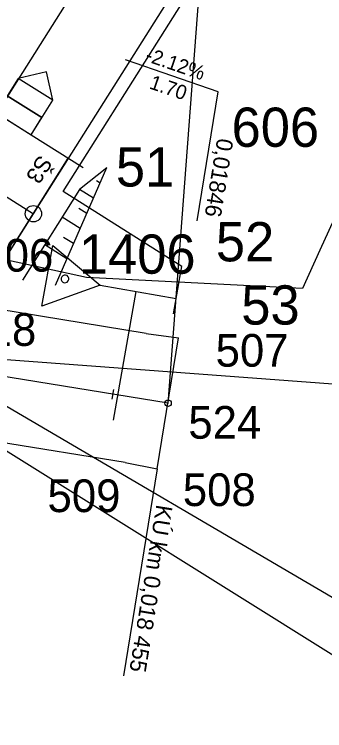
# Model space of a CAD drawing. Extents: x -743546 to -74, y -1128126 to -103.
# Drawn here: x -743168.98 to -743159.49, y -1127109.43 to -1127087.52 of the extents above; entities that cross this region are included whole.
import ezdxf

# ---------------------------------------------------------------- set-up
doc = ezdxf.new("R2010")
doc.units = 0
for name, color, linetype in [('_SVAH - Přesunutá', 7, 'Continuous'), ('_Zabezpečovací zařízení', 7, 'Continuous'), ('_Zabezpečovací zařízení_trasa', 7, 'Continuous'), ('bublina_fialová_čára_tenká', 7, 'Continuous'), ('KOMUNIKACE_KRAJNICE', 7, 'Continuous'), ('křížek', 7, 'Continuous'), ('křížky', 7, 'Continuous'), ('OSA_KOMUNIKACE', 7, 'Continuous'), ('OSA_POP', 7, 'Continuous'), ('SKLONOVNIKY', 7, 'Continuous'), ('SMER_VYS_VYROVNANI', 7, 'Continuous'), ('TRATIVOD', 7, 'Continuous'), ('Vrstva 53', 7, 'Continuous'), ('Vrstva 60', 7, 'Continuous')]:
    doc.layers.add(name, color=color, linetype=linetype)

# ---------------------------------------------------------------- blocks, each defined once
blk = doc.blocks.new('POINT_DISPLAY')
blk.add_line((0, 0), (0, 0))
blk = doc.blocks.new('AeccTickCircle')
blk.add_circle((0, 0), 0.5)

msp = doc.modelspace()

# ---------------------------------------------------------------- linework, layer by layer
at = {"layer": '_SVAH - Přesunutá'}
for p, q in [((-743166.364, -1127092.684), (-743166.469, -1127092.618)), ((-743166.567, -1127093.147), (-743166.987, -1127092.882)), ((-743166.77, -1127093.61), (-743167.012, -1127093.458)), ((-743166.973, -1127094.073), (-743167.521, -1127093.728)), ((-743167.176, -1127094.536), (-743167.482, -1127094.344)), ((-743167.379, -1127095), (-743168.055, -1127094.573))]:
    msp.add_line(p, q, dxfattribs=at)
for points in [[(-743167.343, -1127091.922), (-743169.607, -1127095.509)], [(-743166.158, -1127092.217), (-743166.987, -1127092.882), (-743168.735, -1127095.651)], [(-743166.161, -1127092.221), (-743167.737, -1127095.814)]]:
    msp.add_lwpolyline(points, dxfattribs=at)
at = {"layer": '_Zabezpečovací zařízení'}
for p, q in [((-743168.004, -1127089.286), (-743168.865, -1127089.483)), ((-743167.807, -1127090.147), (-743168.004, -1127089.286)), ((-743168.865, -1127089.483), (-743169.53, -1127090.542)), ((-743167.807, -1127090.147), (-743168.865, -1127089.483)), ((-743169.198, -1127090.012), (-743168.139, -1127090.677)), ((-743168.471, -1127091.206), (-743167.807, -1127090.147)), ((-743169.53, -1127090.542), (-743168.471, -1127091.206)), ((-743168.139, -1127096.449), (-743167.81, -1127094.588)), ((-743167.81, -1127094.588), (-743166.363, -1127095.804)), ((-743164.119, -1127096.681), (-743163.954, -1127095.75)), ((-743166.363, -1127095.804), (-743168.139, -1127096.449)), ((-743166.363, -1127095.804), (-743164.036, -1127096.216)), ((-743165.267, -1127095.997), (-743165.964, -1127099.936))]:
    msp.add_line(p, q, dxfattribs=at)
msp.add_lwpolyline([(-743168.471, -1127091.206), (-743168.139, -1127090.677), (-743169.198, -1127090.012), (-743169.53, -1127090.542), (-743168.471, -1127091.206)], dxfattribs=at)
for start, end in [(79.9608, 259.9608), (259.9608, 79.9608)]:
    msp.add_arc((-743167.437, -1127095.614), 0.118, start, end, dxfattribs=at)
at = {"layer": '_Zabezpečovací zařízení_trasa'}
for points in [[(-743164.036, -1127096.193), (-743163.862, -1127095.231), (-743167.492, -1127092.937), (-743158.53, -1127078.745)], [(-743168.471, -1127091.206), (-743166.88, -1127092.211)]]:
    msp.add_lwpolyline(points, dxfattribs=at)
at = {"layer": 'bublina_fialová_čára_tenká'}
for p, q in [((-743158.823, -1127027.044), (-743164.286, -1127099.423)), ((-743129.509, -1127122.8), (-743175.485, -1127095.847)), ((-743148.502, -1127099.644), (-743174.29, -1127097.707)), ((-743109.419, -1127138.306), (-743174.121, -1127097.814))]:
    msp.add_line(p, q, dxfattribs=at)
at = {"layer": 'KOMUNIKACE_KRAJNICE'}
for p, q in [((-743164.95, -1127097.281), (-743171.211, -1127096.261)), ((-743164.95, -1127097.281), (-743163.96, -1127097.421)), ((-743164.612, -1127101.425), (-743163.96, -1127097.421)), ((-743165.593, -1127101.229), (-743173.53, -1127099.936)), ((-743165.593, -1127101.229), (-743164.612, -1127101.425))]:
    msp.add_line(p, q, dxfattribs=at)
at = {"layer": 'OSA_KOMUNIKACE'}
msp.add_line((-743164.284, -1127099.415), (-743182.5, -1127096.45), dxfattribs=at)
at = {"layer": 'OSA_POP'}
for p, q in [((-743165.99, -1127099.29), (-743165.941, -1127098.994)), ((-743164.612, -1127101.425), (-743165.642, -1127107.754))]:
    msp.add_line(p, q, dxfattribs=at)
at = {"layer": 'SKLONOVNIKY'}
for p, q in [((-743162.751, -1127089.893), (-743165.588, -1127088.917)), ((-743163.394, -1127093.841), (-743162.751, -1127089.893))]:
    msp.add_line(p, q, dxfattribs=at)
at = {"layer": 'SMER_VYS_VYROVNANI'}
msp.add_lwpolyline([(-743143.427, -1127049.192), (-743169.53, -1127090.542)], dxfattribs=at)
at = {"layer": 'TRATIVOD'}
for points in [[(-743175.637, -1127105.086), (-743168.399, -1127093.621), (-743157.384, -1127076.172), (-743151.775, -1127072.311)], [(-743172.796, -1127090.845), (-743168.399, -1127093.621)]]:
    msp.add_lwpolyline(points, dxfattribs=at)
msp.add_circle((-743168.399, -1127093.621), 0.25, dxfattribs=at)
at = {"layer": 'Vrstva 53'}
msp.add_lwpolyline([(-743032.8, -1126884.17), (-743063.8, -1126932.98), (-743082.27, -1126962.07), (-743093.1, -1126978.92), (-743136.47, -1127047.12), (-743147.78, -1127068.8), (-743159.64, -1127094.74), (-743160.17, -1127095.91), (-743166.78, -1127095.57), (-743176.42, -1127093.47), (-743180.17, -1127093.19), (-743180.08, -1127092.14), (-743178.51, -1127091.81), (-743175.35, -1127091.16), (-743150.075, -1127051.72), (-743124.8, -1127012.28), (-743108.67, -1126985.4), (-743080.97, -1126930.41), (-743079.79, -1126928.05), (-743048.51, -1126865.51)], dxfattribs=at)
at = {"layer": 'Vrstva 60'}
for p, q in [((-743167.492, -1127092.937), (-743167.492, -1127092.937)), ((-743168.399, -1127093.621), (-743168.399, -1127093.621)), ((-743163.862, -1127095.231), (-743163.862, -1127095.231)), ((-743164.036, -1127096.216), (-743164.036, -1127096.216)), ((-743163.96, -1127097.421), (-743163.96, -1127097.421)), ((-743164.286, -1127099.423), (-743164.286, -1127099.423)), ((-743165.593, -1127101.229), (-743165.593, -1127101.229)), ((-743164.612, -1127101.425), (-743164.612, -1127101.425))]:
    msp.add_line(p, q, dxfattribs=at)

# ---------------------------------------------------------------- block references
at = {"layer": 'křížek', "xscale": 10, "yscale": 10, "rotation": 61.14491455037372}
for p in [(-743163.96, -1127097.421), (-743164.286, -1127099.423), (-743165.593, -1127101.229), (-743164.612, -1127101.425)]:
    msp.add_blockref('POINT_DISPLAY', p, dxfattribs=at)
at = {"layer": 'křížky', "xscale": 10, "yscale": 10, "rotation": 61.14491455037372}
for p in [(-743167.492, -1127092.937), (-743168.399, -1127093.621), (-743163.862, -1127095.231), (-743164.036, -1127096.216)]:
    msp.add_blockref('POINT_DISPLAY', p, dxfattribs=at)
at = {"layer": 'OSA_POP', "xscale": 0.2, "yscale": 0.19999999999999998, "rotation": -9.247996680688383}
msp.add_blockref('AeccTickCircle', (-743164.284, -1127099.415), dxfattribs=at)

# ---------------------------------------------------------------- texts
at = {"layer": 'OSA_POP'}
msp.add_text('KÚ km 0,018 455', height=0.5, rotation=260.752, dxfattribs=at).set_placement((-743164.636, -1127102.497))
at = {"layer": 'SKLONOVNIKY'}
for s, height, rotation, p in [('-2.12%', 0.44, 341.0149, (-743165.009, -1127088.94)), ('1.70', 0.44, 341.0149, (-743164.882, -1127089.785)), ('0,01846', 0.5, 260.752, (-743162.778, -1127091.293))]:
    msp.add_text(s, height=height, rotation=rotation, dxfattribs=at).set_placement(p)
at = {"layer": 'TRATIVOD'}
msp.add_text('Š3', height=0.5, rotation=238, dxfattribs=at).set_placement((-743168.216, -1127091.792))
at = {"layer": 'Vrstva 60'}
for s, height, p in [('606', 1.2, (-743162.341, -1127091.576)), ('51', 1.2, (-743165.878, -1127092.789)), ('52', 1.2, (-743162.821, -1127095.078)), ('1406', 1.2, (-743167.011, -1127095.456)), ('506', 1, (-743170.024, -1127095.392)), ('53', 1.2, (-743162.044, -1127097.011)), ('518', 1, (-743170.544, -1127097.662)), ('507', 1, (-743162.829, -1127098.299)), ('524', 1, (-743163.663, -1127100.501)), ('508', 1, (-743163.832, -1127102.56)), ('509', 1, (-743167.97, -1127102.745))]:
    msp.add_text(s, height=height, dxfattribs=at).set_placement(p)

doc.saveas('drawing.dxf')
